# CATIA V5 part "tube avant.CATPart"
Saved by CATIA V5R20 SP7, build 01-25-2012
Part number: tube avant
Bounding box of the stored display mesh (mm): x -140 to 18, y -300 to 300, z 25 to 475
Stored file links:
  D:\thinkmotion-MPB\Dropbox\Pack 1 sylvain\CFAO_2010_yyang\yyang\CFAO_2010_yyang\tube avant.CATPart
  D:\thinkmotion-MPB\Dropbox\Pack 1 sylvain\CFAO_2010_yyang\yyang\CFAO_2010_yyang\yyang.CATProduct
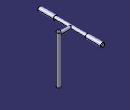
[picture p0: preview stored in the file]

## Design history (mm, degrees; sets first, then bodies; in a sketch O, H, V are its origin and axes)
External parameters (linked from other documents)
  `External.rayon1 de l'antiboue` = 30 mm
  `External.rayon1 du tube` = 21 mm
  `External.rayon2 du tube` = 18 mm
  `External.longueur du tube` = 450 mm
  `External.rayon exterieur du support du guidon` = 15 mm
  `External.rayon interieur du support du guidon` = 12 mm
  `External.demi_longeur du support de guidon` = 150 mm
  `External.rayon du guidon` = 20 mm
  `External.demi_longueur du guidon` = 300 mm
Set1
  Plane1: linked copy from another document
  Point1: linked copy from another document
  Plane2: linked copy from another document
  Point2: linked copy from another document
  Plane3: linked copy from another document
Body1 (main body)
  Sketch1 on Plane1, origin (0, 0, 25), H (1, 0, 0), V (0, 1, 0)
    circle A1 centre (0, 0) radius 18
    point P1 (0, 0)
    reference projected point E1 (0, 0) from Point1
    reference projected point E2 (0, 0) from Point1
    distance A1 E2 = 18 {= `External.rayon2 du tube`}
    coincidence: P1 E1
  Pad1: profile Sketch1, direction (0, 0, 1), length 450 {= `External.longueur du tube`}
  Sketch2 on Plane2, origin (0, 0, 0), H (0, 1, 0), V (0, 0, 1)
    circle A1 centre (0, 450) radius 15
    point P1 (0, 450)
    reference projected point E1 (0, 450) from Point2
    reference projected point E2 (0, 450) from Point2
    circle A2 centre (0, 450) radius 12
    point P2 (0, 450)
    reference projected point E3 (0, 450) from Point2
    reference projected point E4 (0, 450) from Point2
    distance A1 E2 = 15 {= `External.rayon exterieur du support du guidon`}
    distance A2 E4 = 12 {= `External.rayon interieur du support du guidon`}
    coincidence: P1 E1, P2 E3
  Sketch3 on Plane3, origin (0, 0, 0), H (-1, 0, 0), V (0, 0, 1)
    circle A1 centre (120, 450) radius 15
    point P1 (120, 450)
    reference projected point E1 (120, 450) from Point2
    reference projected point E2 (120, 450) from Point2
    circle A2 centre (120, 450) radius 12
    point P2 (120, 450)
    reference projected point E3 (120, 450) from Point2
    reference projected point E4 (120, 450) from Point2
    distance A1 E2 = 15 {= `External.rayon exterieur du support du guidon`}
    distance A2 E4 = 12 {= `External.rayon interieur du support du guidon`}
    coincidence: P1 E1, P2 E3
  Pad2: profile Sketch3, direction (0, 1, 0), length 150 {= `External.demi_longeur du support de guidon`}, mirrored extent
  Pad3: profile Sketch2, direction (-1, 0, 0), up to face of Pad2 from Sketch3.A1
  Sketch4 on start face of Pad2, origin (0, -150, 0), H (1, 0, 0), V (0, 0, 1)
    circle A1 centre (-120, 450) radius 20
    point P1 (-120, 450)
    reference projected point E1 (-120, 450) from Point2
    reference projected point E2 (-120, 450) from Point2
    distance A1 E2 = 20 {= `External.rayon du guidon`}
    coincidence: P1 E1
  Pad4: profile Sketch4, direction (0, -1, 0), length 150 {= `External.demi_longueur du guidon`-`External.demi_longeur du support de guidon`}
  Fillet1: radius 5, on end face of Pad4
  Mirror1: of Pad4, Fillet1, about Plane3
  Fillet2: radius 5, on edge [face of Pad1 from Sketch1.A1 | end face of Pad1]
